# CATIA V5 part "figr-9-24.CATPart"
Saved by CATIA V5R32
Part number: Part2
Bounding box of the stored display mesh (mm): x -72 to 72, y -80 to 90, z -20 to 41.296
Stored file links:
  D:\PROJECTS\Project 2022\CATIA V5 6R 2022\Resources\Part Files\c09_catia_v5_6r2022_prt\c09_catia_v5_6r2022_prt\figr-9-24.CATPart
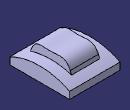
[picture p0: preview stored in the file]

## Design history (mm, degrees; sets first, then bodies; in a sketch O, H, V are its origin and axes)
Body1 (main body)
  Sketch1 on yz-plane, origin (0, 0, 0), H (0, 1, 0), V (0, 0, 1)
    arc A1 centre (5, -170) radius 190.0658 from (-80, 0) to (90, 0) cw
    point P2 (-80, 0)
    point P3 (0, 20)
    line L1 (-80, 0) -> (-80, -20)
    line L2 (-80, -20) -> (90, -20)
    line L3 (90, -20) -> (90, 0)
    coincidence: P2 H, A1 P3, P3 V
    vertical: L1 V, L3 V
    horizontal: L2 H
  Pad1: profile Sketch1, direction (1, 0, 0), length 72, mirrored extent
  Sketch2 on yz-plane, origin (0, 0, 0), H (0, 1, 0), V (0, 0, 1)
    spline S1 through (60, 20) (40, 40) (10, 40) (-10, 40) (-30, 40) (-50, 20)
  Sketch3 on zx-plane, origin (0, 0, 0), H (-1, 0, 0), V (0, 0, 1)
    line L1 (-40, 30) -> (40, 30)
    horizontal: L1 H
  Rib1: profile Sketch2, centre curve Sketch3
